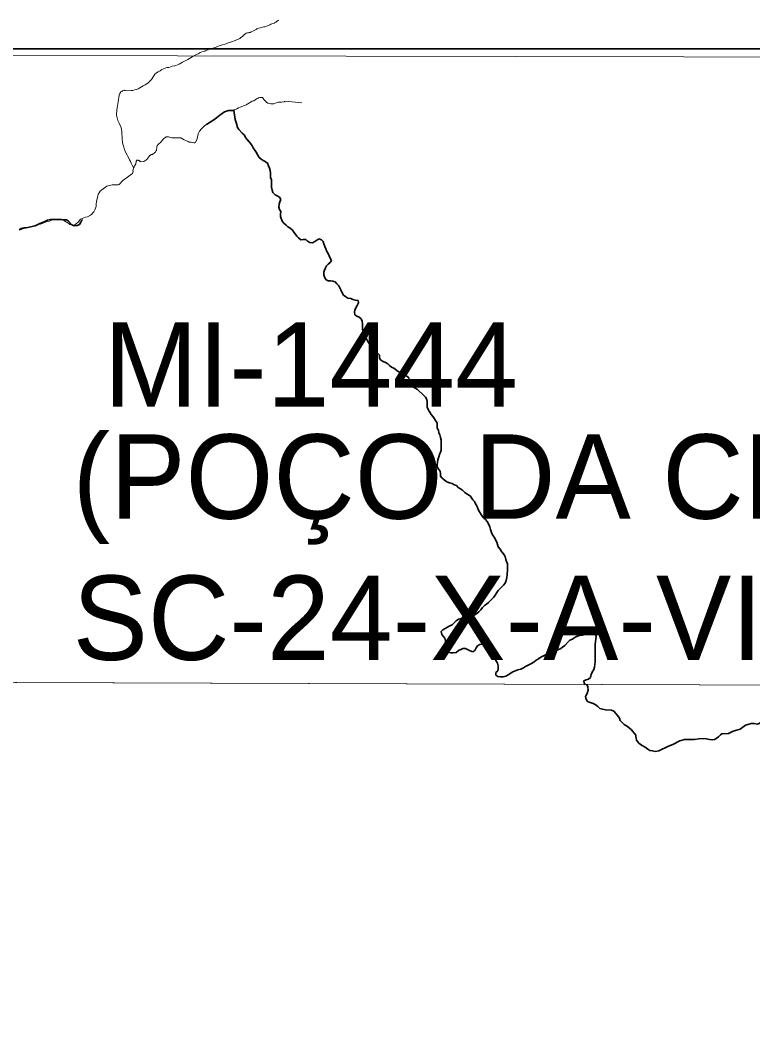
# Model space of a CAD drawing. Extents: x -1643653 to 4543381, y 1624270 to 13878484.
# Drawn here: x 589726 to 594066, y 8918990 to 8924941 of the extents above; entities that cross this region are included whole.
import ezdxf

# ---------------------------------------------------------------- set-up
doc = ezdxf.new("R2010")
doc.units = 0
doc.header["$LTSCALE"] = 200
doc.linetypes.add('LONG_DASH_SHORT_DASH', pattern=[9.9, 6, -1.2, 1.5, -1.2])
doc.layers.add('6', color=7, linetype='Continuous', lineweight=13)
doc.layers.add('60', color=7, linetype='Continuous', lineweight=13)

msp = doc.modelspace()

# ---------------------------------------------------------------- linework, layer by layer
at = {"layer": '6'}
for points in [[(590344.7, 8924524.1), (590346.1, 8924523.9), (590358, 8924520.2), (590383.2, 8924523.4), (590393.5, 8924524), (590404.1, 8924526.7), (590414.4, 8924528.6), (590424.7, 8924532.6), (590445.3, 8924544.2), (590455.6, 8924551.2), (590465.9, 8924557), (590475.9, 8924563.2), (590484.8, 8924569.5), (590494.8, 8924578.4), (590504.2, 8924588.4), (590517, 8924609.5), (590517.1, 8924611), (590524.6, 8924619.7), (590534, 8924627.8), (590543.3, 8924634.2), (590554.6, 8924640.6), (590565.1, 8924647.2), (590585.7, 8924656.2), (590595.8, 8924658.8), (590606, 8924660.2), (590616.3, 8924664), (590626.7, 8924667.2), (590639.5, 8924669.1), (590642.4, 8924669.9), (590647.3, 8924670.5), (590657.6, 8924675), (590667.6, 8924678.8), (590688.5, 8924691.7), (590719.6, 8924707.4), (590729.6, 8924713.1), (590749.9, 8924725.7), (590758.9, 8924730.8), (590770.5, 8924736.7), (590781.1, 8924741.4), (590792, 8924748.1), (590801.7, 8924751.7), (590820, 8924755.7), (590820.5, 8924756.1), (590821.9, 8924758.3), (590825.7, 8924760.6), (590832.6, 8924762.1), (590837.2, 8924763.8), (590843.2, 8924768), (590853.2, 8924770.5), (590864.6, 8924772.2), (590873.8, 8924775), (590883, 8924778.7), (590894.4, 8924783.6), (590904.4, 8924787.2), (590916.9, 8924790.8), (590946.9, 8924800.3), (590957.5, 8924804.8), (590977.5, 8924812.4), (591000.1, 8924819.7), (591023.1, 8924830.1), (591026.5, 8924831.2), (591031.1, 8924835.4), (591044.3, 8924845.6), (591048.9, 8924850.1), (591053.2, 8924853.7), (591065.5, 8924862.8), (591073.3, 8924865.4), (591078.4, 8924865.6), (591082.8, 8924866), (591088.7, 8924867.5), (591094.1, 8924870.2), (591105.1, 8924874.4), (591108, 8924875.9), (591112, 8924879.1), (591116.6, 8924880.1), (591120.9, 8924882.9), (591124.8, 8924885), (591128.7, 8924888.2), (591133.8, 8924890.1), (591139, 8924892.5), (591169.3, 8924900.3), (591175.2, 8924901.1), (591185.6, 8924903.8), (591196.1, 8924907.8), (591205.7, 8924912.7), (591211.1, 8924915.9), (591216, 8924918.4), (591231.2, 8924922.4), (591232.2, 8924923.5), (591240.4, 8924928.8), (591244.5, 8924932.2), (591253.5, 8924937.3), (591256.3, 8924939.6)], [(590992.5, 8924408.9), (590998.2, 8924407.9), (591001.7, 8924410.6), (591009.4, 8924414.9), (591019.6, 8924420.2), (591029, 8924424.2), (591055.7, 8924433.9), (591064.4, 8924438.2), (591073.7, 8924444.1), (591099.9, 8924459.1), (591109.4, 8924462.7), (591118.2, 8924467), (591130.4, 8924475.9), (591134.9, 8924476.9), (591136.3, 8924478.6), (591137.1, 8924478.9), (591145.2, 8924480.7), (591162.1, 8924481.3), (591169.8, 8924470.2), (591176.4, 8924462.5), (591185.8, 8924454.4), (591193.6, 8924448.8), (591202.3, 8924445.7), (591211.4, 8924443.2), (591228.4, 8924443.3), (591248, 8924451.7), (591256.5, 8924453.6), (591265.2, 8924454.9), (591274.8, 8924454.9), (591289.2, 8924456.1), (591290.2, 8924456.7), (591292.7, 8924458.8), (591295.8, 8924459), (591395.2, 8924449.5)], [(590992.5, 8924402.1), (590990.2, 8924402.6), (590973.7, 8924404.6), (590952.7, 8924402.9), (590942.3, 8924398.3), (590932.8, 8924393.6), (590923, 8924387.5), (590914.7, 8924381.7), (590891.1, 8924363.9), (590882.9, 8924358.3), (590876.5, 8924353.5), (590862.7, 8924340.9), (590854.6, 8924335.8), (590835.3, 8924325.4), (590826.3, 8924319.7), (590818, 8924313.8), (590811.3, 8924307.8), (590800.4, 8924295.7), (590789.2, 8924281.4), (590785.1, 8924274.4), (590781.3, 8924266.7), (590778.8, 8924256.9), (590775.1, 8924237.1), (590773.8, 8924233.8), (590764.3, 8924217.2), (590758, 8924212.3), (590755.1, 8924211.9), (590738, 8924216), (590727.2, 8924217.6), (590721.5, 8924220.6), (590706.8, 8924226.4), (590696.7, 8924230.7), (590688.6, 8924236.5), (590677, 8924242.1), (590646.8, 8924242.2), (590635.5, 8924241.6), (590625.2, 8924242.9), (590604.8, 8924247.7), (590590, 8924247.6), (590588.5, 8924247.4), (590574.8, 8924237.1), (590556.4, 8924214), (590548.1, 8924207.6), (590540.8, 8924200.3), (590539, 8924198), (590538.7, 8924197.1), (590538.5, 8924194.4), (590536.1, 8924190.7), (590534.2, 8924168.1), (590532.4, 8924165.1), (590530.3, 8924164.5), (590527.7, 8924157.9), (590523.1, 8924155.6), (590510, 8924144.5), (590501.7, 8924142.9), (590490.8, 8924134.1), (590489.8, 8924130.3), (590488.1, 8924129.4), (590477.2, 8924114.8), (590471.2, 8924109.6), (590459.3, 8924102), (590457.6, 8924101.6), (590440.8, 8924101.2), (590440.2, 8924101.4), (590439, 8924102.9), (590436.2, 8924103), (590432, 8924105.7), (590431, 8924107.3), (590427.5, 8924108.1), (590425.4, 8924110.3), (590416, 8924109.2), (590415.1, 8924105.6), (590413, 8924103.7), (590412.7, 8924103.2), (590411.1, 8924087.9), (590397.2, 8924064.7)], [(590397.2, 8924064.7), (590397.2, 8924064.7), (590389.6, 8924081.3), (590384.3, 8924092), (590380.2, 8924102.3), (590374.6, 8924112.4), (590369.9, 8924122.8), (590352.7, 8924153), (590347.6, 8924162.9), (590342.2, 8924179.5), (590338.2, 8924194.3), (590335, 8924204.5), (590332.3, 8924215.2), (590331, 8924235.1), (590330.9, 8924245.8), (590328.3, 8924265.8), (590328.2, 8924276.7), (590325.6, 8924296.8), (590322, 8924307.9), (590312.8, 8924329.1), (590304.5, 8924346.2)], [(589723, 8923695), (589763.3, 8923710.2), (589780, 8923711.5), (589784.3, 8923712.3), (589805.5, 8923720.1), (589825.2, 8923726.3), (589835.1, 8923728.3), (589846, 8923731.7), (589856.3, 8923735.5), (589866.9, 8923738.3), (589887, 8923745.7), (589899.2, 8923749), (589907.8, 8923751.8), (589918.2, 8923755.6), (589928.5, 8923757.5), (589945.5, 8923758.9), (589949.4, 8923759.5), (589962.9, 8923759.5), (589969.1, 8923759), (589971.3, 8923758.2), (589991.2, 8923749.3), (590013.6, 8923734.5), (590015.6, 8923732.4), (590018, 8923732.1), (590018.8, 8923730), (590019.5, 8923729.4), (590040.4, 8923724.8), (590041.7, 8923725), (590051, 8923729.2), (590060.6, 8923735), (590068.8, 8923742.4), (590083.2, 8923761.2), (590093.2, 8923765), (590103.7, 8923768.5), (590113.7, 8923772.2), (590124.3, 8923774.9), (590141.8, 8923783.6), (590149.8, 8923790.2), (590155.1, 8923795.5), (590162.2, 8923804.2), (590168.8, 8923815.7), (590172.5, 8923825.7), (590175.5, 8923835.3), (590175.7, 8923846.6), (590178.2, 8923866.7), (590185.8, 8923897.6), (590188.8, 8923907.7), (590194.8, 8923917.5), (590200.8, 8923925.8), (590210.7, 8923934.5), (590238.8, 8923955.5), (590271.9, 8923963.9), (590292.3, 8923963.9), (590306.4, 8923963.4), (590312, 8923965.1), (590320.8, 8923973.6), (590326.7, 8923981.9), (590333.3, 8923989.3), (590341.6, 8923996.5), (590361.1, 8924009.5), (590378.2, 8924022.2), (590391.5, 8924031), (590393.5, 8924037.1), (590394.6, 8924044), (590393.9, 8924046.5), (590397.1, 8924063), (590397.2, 8924064.7)], [(574684.9, 8921064.7), (596639.8, 8920989.8), (607636.3, 8920937.2), (626625.7, 8920820.5)]]:
    msp.add_lwpolyline(points, dxfattribs=at)
at = {"layer": '6', "lineweight": 35}
msp.add_lwpolyline([(574695.3, 8924769.6), (626625.7, 8924769.6), (626625.7, 8896026.7), (574695.3, 8896026.7)], close=True, dxfattribs=at)
at = {"layer": '6'}
msp.add_lwpolyline([(585656.3, 8924738.8), (596655.5, 8924715.8), (596639.8, 8920989.8), (585645.8, 8921027.3)], close=True, dxfattribs=at)
at = {"layer": '6', "linetype": 'LONG_DASH_SHORT_DASH', "lineweight": 35}
for points in [[(591402.7, 8923639.7), (591389.2, 8923638.7), (591375.1, 8923649.2), (591364.5, 8923660.2), (591355.4, 8923672.7), (591347.8, 8923684.2), (591338.7, 8923695.2), (591325.6, 8923706.7), (591312, 8923715.7), (591300.9, 8923724.2), (591287.3, 8923736.1), (591278.2, 8923748.7), (591268.1, 8923776.2), (591269, 8923791.8), (591271, 8923805.9), (591262.4, 8923816.9), (591258.8, 8923831.9), (591259.3, 8923848.5), (591263.2, 8923863.1), (591270.2, 8923876.2), (591263.1, 8923890.2), (591249, 8923899.2), (591235.9, 8923905.1), (591223.3, 8923918.6), (591218.8, 8923932.2), (591215.7, 8923949.2), (591215.6, 8923980.3), (591215, 8923993.9), (591208.4, 8924006.9), (591208.3, 8924035.1), (591207.3, 8924048.6), (591203.2, 8924062.6), (591196.1, 8924075.7), (591191.5, 8924091.7), (591177.4, 8924102.2), (591164.8, 8924107.7), (591152.8, 8924115.7), (591142.7, 8924126.2), (591133.1, 8924139.7), (591123.5, 8924157.2), (591105.3, 8924183.2), (591099.7, 8924195.8), (591092.1, 8924207.3), (591082, 8924219.3), (591070.4, 8924231.8), (591060.8, 8924243.8), (591054.8, 8924257.8), (591041.6, 8924270.3), (591021.5, 8924292.8), (591012.4, 8924307.9), (591008.8, 8924321.9), (590998.8, 8924350.2), (590992.5, 8924403.6), (590959.8, 8924405.2), (590935.8, 8924396.5), (590908.7, 8924376.5), (590878.4, 8924353.4), (590830.6, 8924322.3)], [(590095.4, 8923759.3), (590091.6, 8923755.2), (590086.2, 8923742.6), (590078.2, 8923729), (590063.1, 8923721.9), (590045.5, 8923720.3), (590031.9, 8923727.8), (590011.7, 8923748.3), (590000.2, 8923755.8), (589984.1, 8923756.7), (589970.5, 8923758.2), (589955.4, 8923759.1), (589906.1, 8923758.9), (589888.1, 8923754.3), (589876, 8923747.7), (589858, 8923740.1), (589842.9, 8923735.5), (589815.3, 8923721.4), (589779.6, 8923713.2), (589762.1, 8923709.6), (589748.5, 8923709), (589732.9, 8923704.4), (589720.4, 8923696.8)], [(591592.6, 8923388.5), (591579, 8923392.4), (591563.9, 8923394.4), (591549.9, 8923394.8), (591537.8, 8923401.8), (591529.7, 8923412.8), (591525.6, 8923429.9), (591525.1, 8923445.4), (591529, 8923458.5), (591534, 8923471.6), (591540.5, 8923483.7), (591551, 8923493.7), (591563, 8923503.3), (591569.5, 8923515.9), (591562.4, 8923528.9), (591555.8, 8923543.5), (591550.8, 8923557.5), (591542.2, 8923569.5), (591535.6, 8923584.1), (591531.5, 8923598.6), (591525.4, 8923613.6), (591521.4, 8923627.7), (591511.3, 8923637.2), (591495.7, 8923643.6), (591482.6, 8923636.6), (591471.1, 8923628), (591458.1, 8923620.9), (591442, 8923621.3), (591428.9, 8923629.8), (591417.8, 8923640.3), (591402.7, 8923639.7)], [(592179.5, 8922576.1), (592172.9, 8922589.1), (592160.3, 8922603.6), (592151.7, 8922615.6), (592144.1, 8922629.2), (592137.5, 8922646.7), (592137.4, 8922676.8), (592133.8, 8922692.4), (592126.2, 8922705.9), (592114.1, 8922717.9), (592078.8, 8922751.4), (592064.7, 8922758.4), (592052.6, 8922765.8), (592039.5, 8922776.8), (592035, 8922789.9), (592032.9, 8922803.4), (592027.8, 8922819), (592016.2, 8922828.9), (592004.6, 8922837.4), (591990, 8922845.9), (591964.4, 8922857.8), (591938.7, 8922876.3), (591925.1, 8922882.8), (591914, 8922892.8), (591903.9, 8922902.8), (591890.8, 8922911.8), (591876.2, 8922917.2), (591862.6, 8922925.2), (591855, 8922937.2), (591855, 8922953.8), (591844.4, 8922963.3), (591830.8, 8922966.7), (591826.7, 8922982.8), (591817.2, 8922992.8), (591804.6, 8922998.2), (591798.5, 8923010.8), (591793.9, 8923023.8), (591784.8, 8923036.3), (591777.7, 8923051.9), (591770.2, 8923063.9), (591763.6, 8923079.4), (591756.5, 8923094.9), (591752.9, 8923111.5), (591752.8, 8923140.6), (591752.2, 8923155.7), (591745.2, 8923169.2), (591733.1, 8923180.2), (591719.5, 8923184.7), (591707.4, 8923194.2), (591705.8, 8923209.2), (591709.3, 8923222.8), (591722.8, 8923248.9), (591729.2, 8923264), (591727.2, 8923277.6), (591712.1, 8923280), (591697, 8923284), (591684.4, 8923289.5), (591666.8, 8923292.9), (591654.2, 8923299.9), (591641.6, 8923310.4), (591633, 8923323.4), (591627.5, 8923337.9), (591612.8, 8923366), (591602.7, 8923378), (591592.6, 8923388.5)], [(592253.2, 8922202.8), (592237.1, 8922214.8), (592224.5, 8922226.3), (592215.4, 8922237.8), (592214.8, 8922251.9), (592213.3, 8922266.4), (592204.7, 8922278.9), (592196.1, 8922292.5), (592195.5, 8922307), (592197, 8922320.6), (592200.5, 8922334.7), (592205.9, 8922350.8), (592209.9, 8922365.3), (592215.4, 8922378.4), (592219.3, 8922391.5), (592220.3, 8922405.6), (592220.1, 8922452.2), (592215.5, 8922466.8), (592212, 8922481.8), (592205.9, 8922494.4), (592203.8, 8922508.9), (592196.8, 8922520.9), (592195.7, 8922536), (592195.6, 8922551.6), (592179.5, 8922576.1)], [(592243.9, 8921333.6), (592256.4, 8921341.1), (592270.4, 8921349.2), (592284, 8921355.8), (592296.5, 8921368.4), (592308.5, 8921379.5), (592322, 8921388.6), (592338.6, 8921394.2), (592352.2, 8921397.8), (592399.8, 8921408.1), (592415.4, 8921413.7), (592430, 8921422.3), (592443.5, 8921433.4), (592454, 8921445.5), (592464.5, 8921459.1), (592476.5, 8921470.2), (592487.5, 8921478.3), (592499.5, 8921488.4), (592531.6, 8921520.6), (592558.1, 8921558.9), (592589.6, 8921591.7), (592598.1, 8921603.3), (592605.1, 8921618.4), (592609, 8921636.5), (592610, 8921653.1), (592612.4, 8921684.7), (592612.3, 8921702.8), (592611.7, 8921717.8), (592607.2, 8921730.9), (592603.1, 8921743.9), (592599, 8921761), (592587.9, 8921777), (592576.8, 8921790.5), (592568.2, 8921803.5), (592557.6, 8921817.5), (592552.5, 8921832.6), (592548.5, 8921846.1), (592540.9, 8921860.6), (592534.8, 8921873.7), (592525.7, 8921886.2), (592518.6, 8921903.2), (592512.5, 8921920.8), (592507.9, 8921936.3), (592500.3, 8921955.4), (592491.7, 8921968.9), (592481.6, 8921980.9), (592471, 8921990.9), (592461.5, 8922003.4), (592443.3, 8922031.9), (592437.2, 8922044.5), (592431.1, 8922060.5), (592424, 8922072.5), (592417.9, 8922086.6), (592407.8, 8922097.1), (592391.2, 8922120.1), (592374.6, 8922130.6), (592358.9, 8922141), (592345.3, 8922154), (592334.7, 8922163), (592321.2, 8922170.5), (592309.6, 8922181), (592296, 8922186.4), (592284.4, 8922194.4), (592268.8, 8922197.4), (592253.2, 8922202.8)], [(592506, 8921239.8), (592476.8, 8921242.7), (592462.3, 8921242.1), (592448.7, 8921239.1), (592434.7, 8921230.9), (592426.2, 8921220.4), (592419.7, 8921204.3), (592407.2, 8921196.2), (592391.1, 8921201.6), (592364.4, 8921215.6), (592348.8, 8921216), (592336.8, 8921208.9), (592322.2, 8921203.8), (592308.2, 8921192.7), (592290.1, 8921189.6), (592276.1, 8921189.6), (592260.5, 8921193), (592248.4, 8921202.5), (592247.3, 8921216.1), (592246.7, 8921233.1), (592246.7, 8921247.2), (592246.1, 8921260.7), (592242.1, 8921276.3), (592231.5, 8921287.8), (592222.9, 8921299.3), (592219.3, 8921315.4), (592228.8, 8921326.9), (592243.9, 8921333.6)], [(593074.3, 8921000.4), (593067.1, 8921009.3), (593064.5, 8921023.9), (593077.6, 8921029.5), (593092.1, 8921033), (593104.1, 8921044.7), (593108.1, 8921061.2), (593114.6, 8921076.3), (593123, 8921091.4), (593127, 8921105), (593130, 8921120.6), (593130.9, 8921135.7), (593131.8, 8921165.8), (593131.5, 8921240.1), (593135.9, 8921272.3), (593136.9, 8921285.8), (593131.3, 8921299.9), (593117.7, 8921303.8), (593102.1, 8921303.8), (593089.1, 8921299.2), (593074.5, 8921298.6), (593057.5, 8921295), (593038.4, 8921292.9), (593020.8, 8921285.8), (593007.8, 8921279.7), (592997.3, 8921271.1), (592982.7, 8921265.1), (592971.7, 8921255.5), (592951.2, 8921233.8), (592939.2, 8921223.7), (592928.1, 8921215.6), (592915.1, 8921210), (592900.1, 8921201.4), (592881.5, 8921197.8), (592854.4, 8921188.7), (592837.8, 8921178.5), (592824.8, 8921172.9), (592809.8, 8921163.3), (592795.2, 8921155.2), (592781.7, 8921146.1), (592767.7, 8921135), (592751.6, 8921125.4), (592719.5, 8921109.2), (592708, 8921101.1), (592692, 8921094), (592673.4, 8921089.9), (592644.3, 8921077.2), (592615.7, 8921059), (592602.2, 8921051.9), (592586.1, 8921047.8), (592571.5, 8921047.3), (592554.9, 8921049.2), (592543.9, 8921057.2), (592544.3, 8921072.8), (592554.8, 8921082.3), (592557.8, 8921096.9), (592557.7, 8921112), (592553.6, 8921128), (592543.5, 8921143.6), (592537.5, 8921158.1), (592533.9, 8921172.6), (592530.3, 8921189.2), (592525.7, 8921217.3), (592518.1, 8921231.3), (592506, 8921239.8)], [(593082.3, 8921002.1), (593088.7, 8920987.9), (593089.8, 8920968), (593084.4, 8920948.3), (593076.2, 8920935.2), (593075, 8920930.6), (593075.9, 8920921.5), (593084.8, 8920903), (593091.1, 8920899.2), (593119.5, 8920888.7)], [(593119.5, 8920888.7), (593131.8, 8920884.2), (593147.7, 8920872.4), (593160.1, 8920860.8), (593166.7, 8920857.9), (593192.6, 8920851.8), (593227.7, 8920849.4), (593243.1, 8920843.9), (593266.9, 8920816.1), (593275.7, 8920802), (593280.1, 8920789), (593284.9, 8920782.6), (593304.2, 8920765.5), (593322.5, 8920752.4)], [(594030.9, 8920764), (594054.9, 8920770.3), (594073.9, 8920770.6), (594092, 8920768.1), (594103, 8920771.6), (594111.8, 8920776.3), (594138.2, 8920802.2), (594156.9, 8920817.3), (594159.3, 8920821.2), (594159, 8920825), (594150, 8920833.8), (594150.8, 8920840.9), (594161, 8920850.4), (594174.3, 8920856.6), (594180.7, 8920861.6), (594187.3, 8920871.1), (594189.3, 8920877.9), (594182.3, 8920894.6), (594176.2, 8920899.4)], [(593322.5, 8920752.4), (593347.4, 8920734.5), (593372.7, 8920702.2), (593373.5, 8920692.7)], [(593845.9, 8920680.4), (593849, 8920681.9), (593862.8, 8920691.4), (593874.2, 8920704.1), (593881.4, 8920709.6), (593921.2, 8920712.4), (593929.8, 8920715), (593950, 8920724.9), (593989.6, 8920737.7), (593999.3, 8920743.2), (594022.2, 8920761.7), (594030.9, 8920764)], [(593373.5, 8920692.7), (593374.2, 8920684.6), (593377, 8920671.6), (593390.5, 8920655.4), (593406.8, 8920642.9), (593428.8, 8920631.4), (593444, 8920618.6), (593456, 8920611.2), (593471.5, 8920608.3)], [(593471.5, 8920608.3), (593486.6, 8920605.5), (593509.7, 8920608.3), (593567, 8920636.9), (593591.1, 8920645.9)], [(593591.1, 8920645.9), (593634.1, 8920668.6), (593661.5, 8920676.8), (593719.8, 8920675.5), (593745.2, 8920679.2), (593781.7, 8920682), (593808.2, 8920676), (593827.3, 8920675.2), (593837.8, 8920676.5), (593845.9, 8920680.4)]]:
    msp.add_lwpolyline(points, dxfattribs=at)
at = {"layer": '6'}
msp.add_spline([(590304.5, 8924346.2), (590297.2, 8924376.4), (590301.6, 8924419.9), (590308.1, 8924468.9), (590323.3, 8924514.7), (590344.7, 8924524.1)], degree=3, dxfattribs=at)
at = {"layer": '60', "lineweight": 25}
msp.add_spline([(814781, 9009175.5), (814787.2, 9009173.4), (814796.9, 9009173.4), (814799.4, 9009172.4), (814805.1, 9009174.5), (814805.6, 9009176.5), (814811.7, 9009179.5), (814811.7, 9009179.5), (814801.5, 9009181), (814790.7, 9009181.5), (814784.1, 9009183.1), (814777.4, 9009185.1), (814778.4, 9009175.5)], degree=3, dxfattribs=at)

# ---------------------------------------------------------------- texts
at = {"layer": '6'}
for s, p in [('MI-1444', (590221.3, 8922649.4)), ('(POÇO DA CRUZ)', (590036.9, 8921984.9)), ('SC-24-X-A-VI', (590036.9, 8921147.9))]:
    msp.add_text(s, height=500, dxfattribs=at).set_placement(p)

doc.saveas('drawing.dxf')
